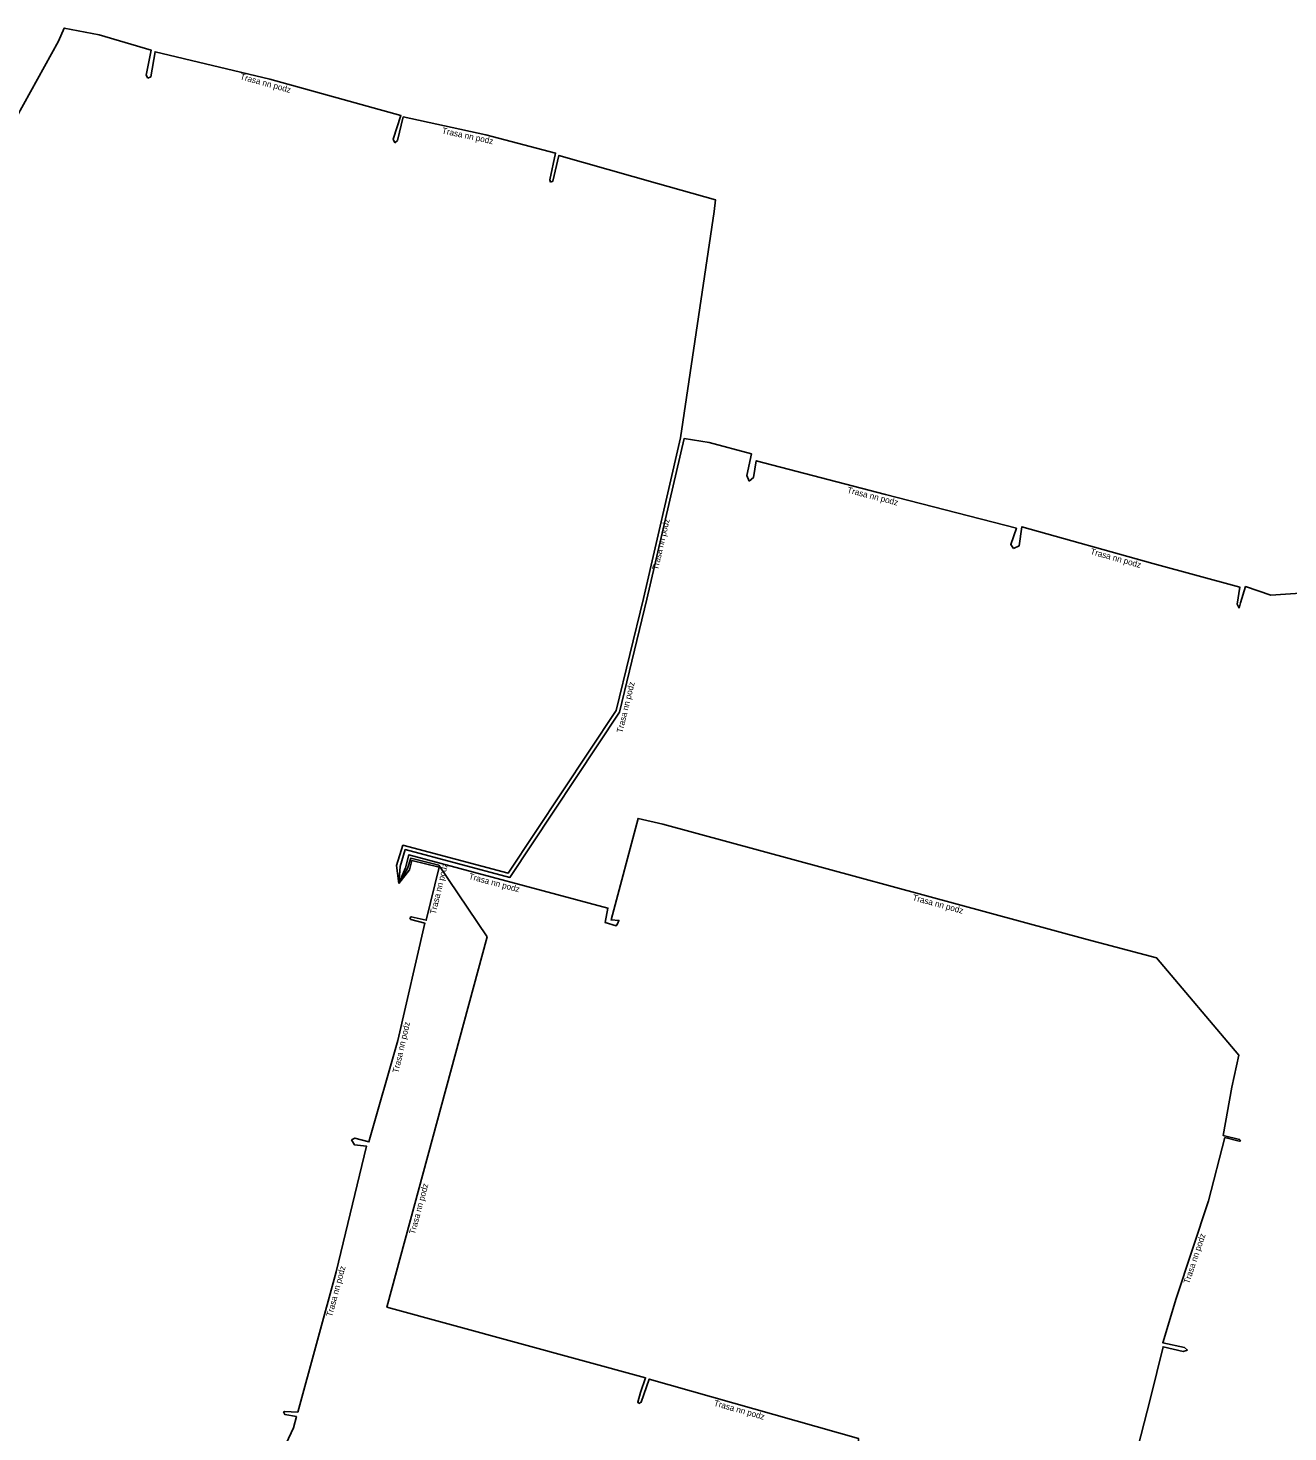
# Model space of a CAD drawing. Extents: x -843786 to -842968, y -1003095 to -1002172.
# Drawn here: x -843348 to -843245, y -1002797.2 to -1002682.4 of the extents above; entities that cross this region are included whole.
import ezdxf

# ---------------------------------------------------------------- set-up
doc = ezdxf.new("R2010")
doc.units = 0
doc.layers.add('Spojnice NN', color=7, linetype='Continuous')
doc.layers.add('Vrstva 20', color=7, linetype='Continuous')

msp = doc.modelspace()

# ---------------------------------------------------------------- linework, layer by layer
at = {"layer": 'Spojnice NN'}
for points in [[(-843338.21, -1002686.49), (-843338.36, -1002686.24), (-843337.94, -1002684.21), (-843342.2, -1002682.96), (-843345.06, -1002682.4), (-843345.52, -1002683.48), (-843351.29, -1002693.83), (-843355.99, -1002706.66), (-843357.86, -1002713.72), (-843356.88, -1002713.95), (-843356.68, -1002714.2)], [(-843318.02, -1002691.79), (-843318.17, -1002691.48), (-843317.53, -1002689.55), (-843328.24, -1002686.59), (-843337.63, -1002684.34), (-843337.99, -1002686.4), (-843338.21, -1002686.49)], [(-843305.29, -1002695.01), (-843305.35, -1002694.81), (-843304.89, -1002692.63), (-843310.59, -1002691.13), (-843317.34, -1002689.67), (-843317.81, -1002691.59), (-843318.02, -1002691.79)], [(-843317.69, -1002752.35), (-843317.88, -1002750.88), (-843317.37, -1002749.22), (-843308.75, -1002751.5), (-843299.94, -1002738.21), (-843297.7, -1002729.04), (-843294.66, -1002715.9), (-843291.91, -1002697.4), (-843291.81, -1002696.44), (-843296.55, -1002695.1), (-843304.61, -1002692.82), (-843305.12, -1002694.93), (-843305.29, -1002695.01)], [(-843317.69, -1002752.35), (-843317.59, -1002750.96), (-843317.17, -1002749.58), (-843308.62, -1002751.85), (-843299.66, -1002738.33), (-843297.41, -1002729.11), (-843294.37, -1002715.96), (-843292.33, -1002716.28), (-843288.87, -1002717.22), (-843289.24, -1002719), (-843289.06, -1002719.44)], [(-843267.44, -1002724.96), (-843267.67, -1002724.62), (-843267.21, -1002723.3), (-843277.9, -1002720.54), (-843288.48, -1002717.78), (-843288.71, -1002719.16), (-843289.06, -1002719.44)], [(-843248.99, -1002729.84), (-843249.16, -1002729.5), (-843248.93, -1002728.12), (-843256.06, -1002726.17), (-843266.75, -1002723.18), (-843266.98, -1002724.73), (-843267.44, -1002724.96)], [(-843222.13, -1002729.57), (-843222.14, -1002729.28), (-843221.85, -1002728.18), (-843225.13, -1002727.32), (-843246.4, -1002728.76), (-843248.47, -1002728.07), (-843248.87, -1002729.39), (-843248.99, -1002729.84)], [(-843299.81, -1002755.64), (-843299.7, -1002755.37), (-843300.34, -1002755.32), (-843298.14, -1002747.03), (-843296.11, -1002747.51), (-843261.41, -1002756.92), (-843255.74, -1002758.42), (-843249.01, -1002766.39), (-843249.6, -1002769), (-843250.29, -1002772.96), (-843248.96, -1002773.28), (-843248.85, -1002773.38)], [(-843317.69, -1002752.35), (-843317, -1002751.11), (-843316.72, -1002750.29), (-843314.44, -1002750.86), (-843310.48, -1002756.7), (-843318.67, -1002786.99), (-843297.53, -1002792.77), (-843297.93, -1002793.96), (-843298.17, -1002794.75), (-843298.08, -1002794.88)], [(-843317.69, -1002752.35), (-843317.16, -1002751.06), (-843316.87, -1002750), (-843300.61, -1002754.36), (-843300.83, -1002755.55), (-843299.93, -1002755.8), (-843299.81, -1002755.64)], [(-843316.81, -1002755.16), (-843316.68, -1002755.07), (-843315.46, -1002755.35), (-843314.41, -1002751.01), (-843316.64, -1002750.48), (-843316.83, -1002751.22), (-843317.69, -1002752.35)], [(-843321.56, -1002773.32), (-843321.29, -1002773.16), (-843320.15, -1002773.48), (-843317.79, -1002765.18), (-843315.58, -1002755.58), (-843316.71, -1002755.29), (-843316.81, -1002755.16)], [(-843327.13, -1002795.55), (-843327.06, -1002795.51), (-843325.96, -1002795.57), (-843322.83, -1002784.1), (-843320.34, -1002773.84), (-843321.32, -1002773.73), (-843321.56, -1002773.32)], [(-843248.85, -1002773.38), (-843248.98, -1002773.42), (-843250.16, -1002773.12), (-843251.49, -1002778.29), (-843254.15, -1002786.27), (-843255.24, -1002789.9), (-843253.47, -1002790.29), (-843253.21, -1002790.51)], [(-843253.21, -1002790.51), (-843253.56, -1002790.61), (-843255.21, -1002790.23), (-843256.24, -1002794.42), (-843259.14, -1002805.68), (-843260.35, -1002810.99), (-843258.78, -1002811.11), (-843258.83, -1002811.93)], [(-843298.08, -1002794.88), (-843297.9, -1002794.76), (-843297.22, -1002792.87), (-843280.11, -1002797.74), (-843280.08, -1002798.95), (-843280.2, -1002799.43), (-843280.12, -1002799.7)], [(-843336.39, -1002817.37), (-843336.08, -1002817.17), (-843335.08, -1002817.38), (-843334.09, -1002813.46), (-843326.32, -1002796.86), (-843326.08, -1002795.93), (-843327.02, -1002795.77), (-843327.13, -1002795.55)]]:
    msp.add_lwpolyline(points, dxfattribs=at)

# ---------------------------------------------------------------- texts
at = {"layer": 'Vrstva 20'}
for rotation, p in [(344.5674, (-843330.72, -1002686.58)), (347.8417, (-843314.21, -1002691.01)), (345.5306, (-843281.08, -1002720.39)), (76.9846, (-843296.51, -1002726.75)), (344.3787, (-843261.2, -1002725.41)), (76.2683, (-843299.42, -1002740.07)), (76.3153, (-843314.69, -1002754.9)), (344.9835, (-843312.02, -1002751.97)), (344.8274, (-843275.74, -1002753.71)), (77.0386, (-843317.74, -1002767.88)), (74.8828, (-843316.39, -1002781.07)), (71.5629, (-843253.08, -1002785.12)), (74.7448, (-843323.17, -1002787.82)), (344.1273, (-843291.98, -1002795.04))]:
    msp.add_text('Trasa nn podz', height=0.5, rotation=rotation, dxfattribs=at).set_placement(p)

doc.saveas('drawing.dxf')
